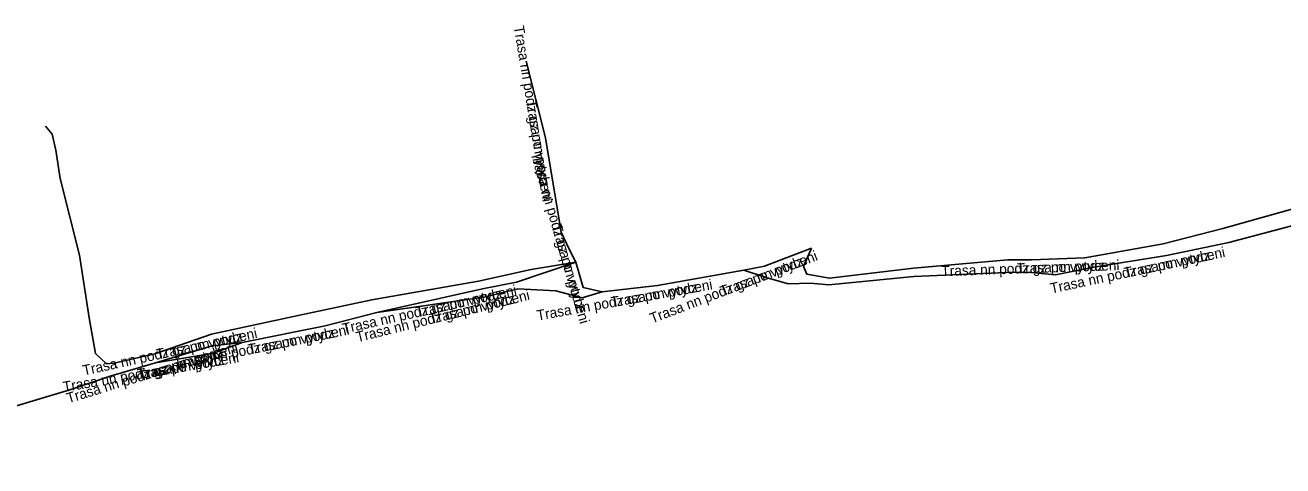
# Model space of a CAD drawing. Extents: x -876384 to -875659, y -1020218 to -1019588.
# Drawn here: x -876029.1 to -875967.7, y -1019869.6 to -1019848.1 of the extents above; entities that cross this region are included whole.
import ezdxf

# ---------------------------------------------------------------- set-up
doc = ezdxf.new("R2010")
doc.units = 0
doc.layers.add('Popiskový text - Ostatní atributy Trasy', color=7, linetype='Continuous')
doc.layers.add('Spojnice NN', color=7, linetype='Continuous')

msp = doc.modelspace()

# ---------------------------------------------------------------- linework, layer by layer
at = {"layer": 'Spojnice NN'}
for points in [[(-876002.24, -1019859.68), (-876002.56, -1019859.05), (-876002.96, -1019858.22), (-876003.72, -1019853.61), (-876004.66, -1019849.88)], [(-876002.24, -1019859.68), (-876002.56, -1019859.05), (-876002.96, -1019858.22), (-876003.72, -1019853.61), (-876004.66, -1019849.88)], [(-875994.05, -1019860.07), (-875992.96, -1019860.43), (-875991.88, -1019860.74), (-875990.79, -1019860.7), (-875989.9, -1019860.79), (-875985.75, -1019860.38), (-875981.22, -1019860.18), (-875980.21, -1019860.17), (-875978.83, -1019860.29), (-875976.96, -1019859.92), (-875973.42, -1019859.36), (-875970.38, -1019858.72), (-875964.6, -1019857.19), (-875959.81, -1019856.06), (-875956.63, -1019856.03), (-875954.62, -1019855.32), (-875953.85, -1019854.36), (-875953.58, -1019852.61), (-875953.66, -1019852.17)], [(-875994.05, -1019860.07), (-875992.96, -1019860.43), (-875991.88, -1019860.74), (-875990.79, -1019860.7), (-875989.9, -1019860.79), (-875985.75, -1019860.38), (-875981.22, -1019860.18), (-875980.21, -1019860.17), (-875978.83, -1019860.29), (-875976.96, -1019859.92), (-875973.42, -1019859.36), (-875970.38, -1019858.72), (-875964.6, -1019857.19), (-875959.81, -1019856.06), (-875956.63, -1019856.03), (-875954.62, -1019855.32), (-875953.85, -1019854.36), (-875953.58, -1019852.61), (-875953.66, -1019852.17)], [(-876002.24, -1019859.68), (-876004.42, -1019860.04), (-876006.99, -1019860.61), (-876012.2, -1019861.51), (-876016.02, -1019862.32), (-876020.02, -1019863.19), (-876022.78, -1019864.14), (-876024.77, -1019864.61), (-876025.15, -1019864.63), (-876025.69, -1019864.13), (-876025.99, -1019862.4), (-876026.47, -1019859.34), (-876027.41, -1019855.6), (-876027.62, -1019854.21), (-876027.79, -1019853.44), (-876028.12, -1019853.04)], [(-876002.24, -1019859.68), (-876004.42, -1019860.04), (-876006.99, -1019860.61), (-876012.2, -1019861.51), (-876016.02, -1019862.32), (-876020.02, -1019863.19), (-876022.78, -1019864.14), (-876024.77, -1019864.61), (-876025.15, -1019864.63), (-876025.69, -1019864.13), (-876025.99, -1019862.4), (-876026.47, -1019859.34), (-876027.41, -1019855.6), (-876027.62, -1019854.21), (-876027.79, -1019853.44), (-876028.12, -1019853.04)], [(-875990.74, -1019859), (-875991.13, -1019859.89), (-875990.97, -1019860.26), (-875989.87, -1019860.46), (-875985.77, -1019859.97), (-875981.16, -1019859.57), (-875980, -1019859.56), (-875977.41, -1019859.47), (-875973.58, -1019858.79), (-875970.66, -1019858.04), (-875965.85, -1019856.69), (-875965.24, -1019856.25), (-875965.3, -1019854.66), (-875965.67, -1019854.53)], [(-875990.74, -1019859), (-875991.13, -1019859.89), (-875990.97, -1019860.26), (-875989.87, -1019860.46), (-875985.77, -1019859.97), (-875981.16, -1019859.57), (-875980, -1019859.56), (-875977.41, -1019859.47), (-875973.58, -1019858.79), (-875970.66, -1019858.04), (-875965.85, -1019856.69), (-875965.24, -1019856.25), (-875965.3, -1019854.66), (-875965.67, -1019854.53)], [(-875994.05, -1019860.07), (-875993.04, -1019859.88), (-875990.74, -1019859)], [(-875994.05, -1019860.07), (-875993.04, -1019859.88), (-875990.74, -1019859)], [(-876002.24, -1019859.68), (-876005.14, -1019860.66), (-876006.79, -1019860.98), (-876011.95, -1019862.14)], [(-876002.24, -1019859.68), (-876005.14, -1019860.66), (-876006.79, -1019860.98), (-876011.95, -1019862.14)], [(-876000.96, -1019861.13), (-876001.88, -1019860.92), (-876002.24, -1019859.68)], [(-876000.96, -1019861.13), (-876001.88, -1019860.92), (-876002.24, -1019859.68)], [(-876000.96, -1019861.13), (-875998.25, -1019860.82), (-875994.05, -1019860.07)], [(-876000.96, -1019861.13), (-875998.25, -1019860.82), (-875994.05, -1019860.07)], [(-876011.95, -1019862.14), (-876006.73, -1019861.39), (-876005.07, -1019860.98), (-876003.22, -1019861.07), (-876001.93, -1019861.41), (-876000.96, -1019861.13)], [(-876011.95, -1019862.14), (-876006.73, -1019861.39), (-876005.07, -1019860.98), (-876003.22, -1019861.07), (-876001.93, -1019861.41), (-876000.96, -1019861.13)], [(-876011.95, -1019862.14), (-876014.48, -1019862.78), (-876018.52, -1019863.59)], [(-876011.95, -1019862.14), (-876014.48, -1019862.78), (-876018.52, -1019863.59)], [(-876018.52, -1019863.59), (-876019.99, -1019863.75), (-876022.75, -1019864.59)], [(-876018.52, -1019863.59), (-876019.93, -1019864.11), (-876022.75, -1019864.59)], [(-876018.52, -1019863.59), (-876019.99, -1019863.75), (-876022.75, -1019864.59)], [(-876018.52, -1019863.59), (-876019.93, -1019864.11), (-876022.75, -1019864.59)], [(-876022.75, -1019864.59), (-876024.97, -1019865.23), (-876026.93, -1019865.91), (-876031.84, -1019867.37), (-876036.61, -1019868.68), (-876039.29, -1019869.18), (-876042.44, -1019869.59), (-876044.13, -1019869.61)], [(-876022.75, -1019864.59), (-876024.97, -1019865.23), (-876026.93, -1019865.91), (-876031.84, -1019867.37), (-876036.61, -1019868.68), (-876039.29, -1019869.18), (-876042.44, -1019869.59), (-876044.13, -1019869.61)]]:
    msp.add_lwpolyline(points, dxfattribs=at)

# ---------------------------------------------------------------- texts
at = {"layer": 'Popiskový text - Ostatní atributy Trasy'}
for s, rotation, p in [('Trasa nn podz gz po vytyceni', 279.36152, (-876005.273, -1019848.185)), ('Trasa nn podz', 279.36152, (-876004.674, -1019851.821)), ('Trasa nn podz gz po vytyceni', 286.18921, (-876004.458, -1019854.373)), ('Trasa nn podz', 286.18921, (-876003.431, -1019857.912)), ('Trasa nn podz gz po vytyceni', 20.93729, (-875998.519, -1019862.672)), ('Trasa nn podz gz po vytyceni', 11.88866, (-875979.033, -1019861.206)), ('Trasa nn podz', 11.88866, (-875975.427, -1019860.447)), ('Trasa nn podz', 20.93729, (-875995.077, -1019861.355)), ('Trasa nn podz gz po vytyceni', 1.99017, (-875984.398, -1019860.363)), ('Trasa nn podz', 1.99017, (-875980.715, -1019860.235)), ('Trasa nn podz gz po vytyceni', 10.12467, (-876004.104, -1019862.526)), ('Trasa nn podz gz po vytyceni', 12.66981, (-876013.58, -1019863.173)), ('Trasa nn podz gz po vytyceni', 13.8737, (-876012.9, -1019863.584)), ('Trasa nn podz', 12.66981, (-876009.985, -1019862.364)), ('Trasa nn podz', 10.12467, (-876000.477, -1019861.878)), ('Trasa nn podz', 13.8737, (-876009.323, -1019862.7)), ('Trasa nn podz gz po vytyceni', 12.27072, (-876026.253, -1019865.21)), ('Trasa nn podz gz po vytyceni', 11.3372, (-876021.792, -1019864.909)), ('Trasa nn podz', 11.3372, (-876018.179, -1019864.185)), ('Trasa nn podz gz po vytyceni', 16.92751, (-876027.01, -1019866.566)), ('Trasa nn podz', 12.27072, (-876022.653, -1019864.427)), ('Trasa nn podz gz po vytyceni', 9.65989, (-876027.226, -1019866.011)), ('Trasa nn podz', 9.65989, (-876023.593, -1019865.393)), ('Trasa nn podz', 16.92751, (-876023.484, -1019865.493))]:
    msp.add_text(s, height=0.5, rotation=rotation, dxfattribs=at).set_placement(p)

doc.saveas('drawing.dxf')
